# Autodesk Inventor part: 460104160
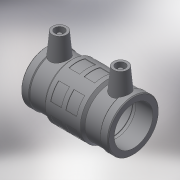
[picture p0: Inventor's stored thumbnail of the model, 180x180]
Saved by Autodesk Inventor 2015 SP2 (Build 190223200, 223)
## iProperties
Created: 2017-06
Part Number: 460104160
Material: Generic
Description: PLASSON LIGHTFIT COUPLER 160
Document SubType Name: Modeling
Designer: KIM
Mass: 89.5427 g
Surface Area: 304.58 cm^2
Volume: 89.5427 cm^3
Density: 1 g/cm^3
Appearance: Default
Author: KIM
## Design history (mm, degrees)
derived "460104.ipt"
feature "Solid1::460104.ipt"
tag "TaggingFeature1"
body "Solid1"
other parameters: "d13" = 198, "d14" = 17.6296, "d15" = 97, "d16" = 97, "d17" = 158.4, "d19" = 3.52592, "d20" = 168 deg, "d22" = 181.42, "d23" = 193, "d24" = 175.9774, "d25" = 135 deg, "d26" = 79.2, "d27" = 135 deg, "d29" = 104, "d35" = 15, "d39" = 5 deg, "d44" = 4, "d46" = 14, "d47" = 0, "d52" = 189.14, "d53" = 9.9, "d54" = 9.9, "d55" = 9.9, "d56" = 35 deg, "d58" = 360 deg, "d60" = 19.4, "d61" = 135 deg, "d62" = 83.16, "d63" = 3, "d64" = 0, "L_" = 198, "L_1" = 97, "D_" = 193, "A_" = 104, "d_2" = 12
